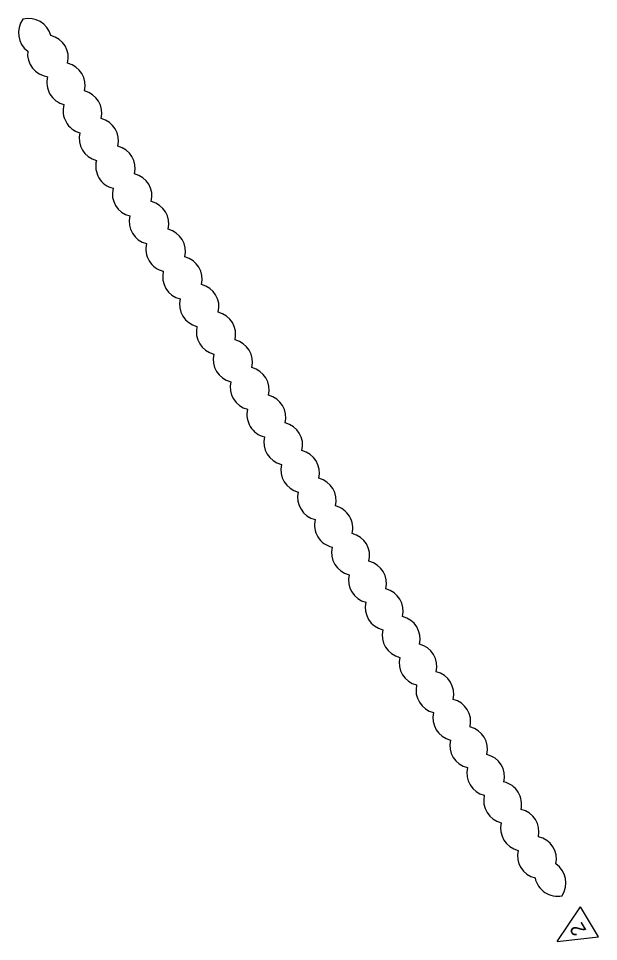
# Model space of a CAD drawing. Extents: x 2640307 to 2643631, y 679117 to 682232.
# Drawn here: x 2640307.3 to 2640555.9, y 680205.9 to 680601.7 of the extents above; entities that cross this region are included whole.
import ezdxf

# ---------------------------------------------------------------- set-up
doc = ezdxf.new("R2010")
doc.units = 0
doc.layers.add('BR_AUTO DIMENSION', color=7, linetype='Continuous')
doc.layers.add('BR_TEXT', color=7, linetype='Continuous')

msp = doc.modelspace()

# ---------------------------------------------------------------- linework, layer by layer
at = {"layer": 'BR_AUTO DIMENSION'}
for p, q in [((2640538.13, 680205.86), (2640548.14, 680220.68)), ((2640555.9, 680207.84), (2640548.14, 680220.68)), ((2640538.13, 680205.86), (2640555.9, 680207.84))]:
    msp.add_line(p, q, dxfattribs=at)
for centre, radius, start, end in [((2640317.05, 680595.56), 9.8, 143.4499, 233.4499), ((2640311.68, 680591.92), 9.8, 14.7856, 104.7856), ((2640318.81, 680584.9), 9.81, 346.1513, 76.1513), ((2640320.95, 680586.49), 9.81, 172.9835, 262.9835), ((2640325.99, 680573.03), 9.81, 346.1513, 76.1513), ((2640329.23, 680574.26), 9.8, 165.2282, 255.2282), ((2640333.16, 680561.16), 9.81, 346.1513, 76.1513), ((2640336.18, 680562.16), 9.81, 164.5362, 254.5362), ((2640340.34, 680549.29), 9.81, 346.1513, 76.1513), ((2640343.07, 680550.29), 9.81, 165.702, 255.702), ((2640347.51, 680537.42), 9.81, 346.1513, 76.1513), ((2640350.16, 680538.41), 9.81, 165.9838, 255.9838), ((2640354.68, 680525.55), 9.81, 346.1513, 76.1513), ((2640357.31, 680526.55), 9.81, 166.1269, 256.1269), ((2640361.86, 680513.69), 9.81, 346.1513, 76.1513), ((2640364.48, 680514.69), 9.81, 166.2175, 256.2175), ((2640369.03, 680501.82), 9.81, 346.1513, 76.1513), ((2640371.67, 680502.84), 9.81, 166.2816, 256.2816), ((2640376.21, 680489.95), 9.81, 346.1513, 76.1513), ((2640378.87, 680491), 9.81, 166.33, 256.33), ((2640383.38, 680478.08), 9.81, 346.1513, 76.1513), ((2640386.09, 680479.16), 9.81, 166.3683, 256.3683), ((2640390.55, 680466.21), 9.81, 346.1513, 76.1513), ((2640393.31, 680467.32), 9.81, 166.3995, 256.3995), ((2640397.73, 680454.35), 9.81, 346.1513, 76.1513), ((2640400.53, 680455.49), 9.81, 166.4256, 256.4256), ((2640404.9, 680442.48), 9.81, 346.1513, 76.1513), ((2640407.76, 680443.66), 9.81, 166.4478, 256.4478), ((2640412.07, 680430.61), 9.81, 346.1514, 76.1514), ((2640415, 680431.83), 9.81, 166.4671, 256.4671), ((2640419.25, 680418.74), 9.81, 346.1591, 76.1591), ((2640422.24, 680420.01), 9.81, 166.484, 256.484), ((2640426.43, 680406.87), 9.81, 346.1745, 76.1745), ((2640429.48, 680408.18), 9.81, 166.4989, 256.4989), ((2640433.61, 680395.01), 9.81, 346.1915, 76.1915), ((2640436.73, 680396.36), 9.81, 166.5123, 256.5123), ((2640440.79, 680383.14), 9.81, 346.2107, 76.2107), ((2640443.98, 680384.54), 9.81, 166.5217, 256.5217), ((2640447.98, 680371.28), 9.81, 346.2324, 76.2324), ((2640451.23, 680372.72), 9.81, 166.5223, 256.5223), ((2640455.18, 680359.42), 9.81, 346.2574, 76.2574), ((2640458.48, 680360.9), 9.81, 166.5223, 256.5223), ((2640462.38, 680347.57), 9.81, 346.2864, 76.2864), ((2640465.73, 680349.08), 9.81, 166.5223, 256.5223), ((2640469.59, 680335.72), 9.81, 346.3207, 76.3207), ((2640472.98, 680337.25), 9.81, 166.5223, 256.5223), ((2640476.8, 680323.87), 9.81, 346.3622, 76.3622), ((2640480.23, 680325.43), 9.81, 166.5223, 256.5223), ((2640484.03, 680312.02), 9.81, 346.4138, 76.4138), ((2640487.48, 680313.61), 9.81, 166.5223, 256.5223), ((2640491.27, 680300.19), 9.81, 346.4804, 76.4804), ((2640494.73, 680301.79), 9.81, 166.5223, 256.5223), ((2640498.52, 680288.35), 9.81, 346.5711, 76.5711), ((2640501.98, 680289.97), 9.81, 166.5223, 256.5223), ((2640505.81, 680276.53), 9.81, 346.7052, 76.7052), ((2640509.23, 680278.15), 9.81, 166.5223, 256.5223), ((2640513.13, 680264.73), 9.81, 346.9351, 76.9351), ((2640516.48, 680266.33), 9.81, 166.5223, 256.5223), ((2640520.56, 680252.94), 9.81, 347.504, 77.504), ((2640523.73, 680254.5), 9.81, 166.5223, 256.5223), ((2640528.03, 680241.24), 9.81, 347.6146, 77.6146), ((2640530.98, 680242.68), 9.81, 166.5223, 256.5223), ((2640532.14, 680230.99), 9.81, 326.1097, 56.1097), ((2640538.3, 680235.13), 9.81, 191.6634, 281.6634)]:
    msp.add_arc(centre, radius, start, end, dxfattribs=at)

# ---------------------------------------------------------------- texts
at = {"layer": 'BR_TEXT'}
msp.add_text('2', height=6.25, rotation=121.1513, dxfattribs=at).set_placement((2640550.9, 680210.7))

doc.saveas('drawing.dxf')
